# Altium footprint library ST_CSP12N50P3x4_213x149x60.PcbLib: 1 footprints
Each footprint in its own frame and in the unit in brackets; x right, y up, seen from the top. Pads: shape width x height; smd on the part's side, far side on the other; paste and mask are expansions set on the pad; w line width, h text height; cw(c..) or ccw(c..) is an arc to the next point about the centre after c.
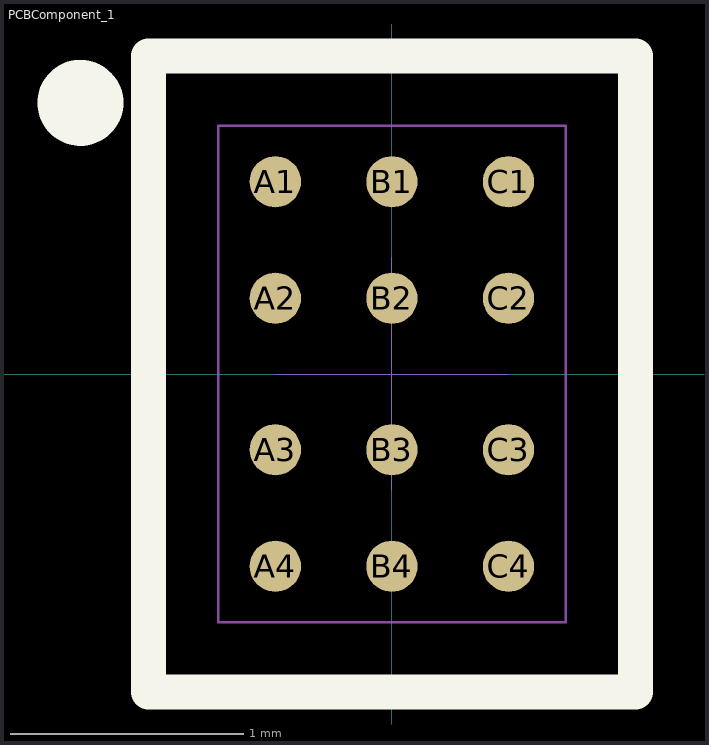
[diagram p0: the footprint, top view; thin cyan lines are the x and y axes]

## PCBComponent_1 [mm]
pads (12):
  round 0.22 smd paste-20 mask+0.04: A1(-0.5,0.825) A2(-0.5,0.325) A3(-0.5,-0.325) A4(-0.5,-0.825) B1(0,0.825) B2(0,0.325) B3(0,-0.325) B4(0,-0.825) C1(0.5,0.825) C2(0.5,0.325) C3(0.5,-0.325) C4(0.5,-0.825)
Top Overlay:
  circle w0.3: c-1.336,1.163 r0.034
  lines w0.15: -1.045,-1.365 -1.045,1.365 1.045,1.365 1.045,-1.365 -1.045,-1.365
Top Paste:
  rectangle: 0.39,-0.935 0.61,-0.715
  rectangle: -0.11,-0.935 0.11,-0.715
  rectangle: -0.61,-0.935 -0.39,-0.715
  rectangle: 0.39,-0.435 0.61,-0.215
  rectangle: -0.11,-0.435 0.11,-0.215
  rectangle: -0.61,-0.435 -0.39,-0.215
  rectangle: 0.39,0.215 0.61,0.435
  rectangle: -0.11,0.215 0.11,0.435
  rectangle: -0.61,0.215 -0.39,0.435
  rectangle: 0.39,0.715 0.61,0.935
  rectangle: -0.11,0.715 0.11,0.935
  rectangle: -0.61,0.715 -0.39,0.935
Mechanical 15:
  lines w0.001: -0.5,0 0.5,0 ; 0,-0.5 0,0.5
  lines w0.01: -0.745,-1.065 -0.745,1.065 0.745,1.065 0.745,-1.065 -0.745,-1.065
3D body: height 0.66, standoff 0.2, extent -0.745,-1.065 0.745,1.065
